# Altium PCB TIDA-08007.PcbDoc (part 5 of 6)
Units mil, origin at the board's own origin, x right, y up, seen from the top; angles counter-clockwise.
Board outline 4212.6 x 2047.24 mil, 10 copper layers (Top Layer, GND 1, Signal Layer 1, GND 2, Split PWR 1, Split PWR 2, GND 3, Signal Layer 2, GND 4, Bottom Layer), stack 66.4 mil thick; 291 components, 178 nets, 1281 pads, 873 vias.
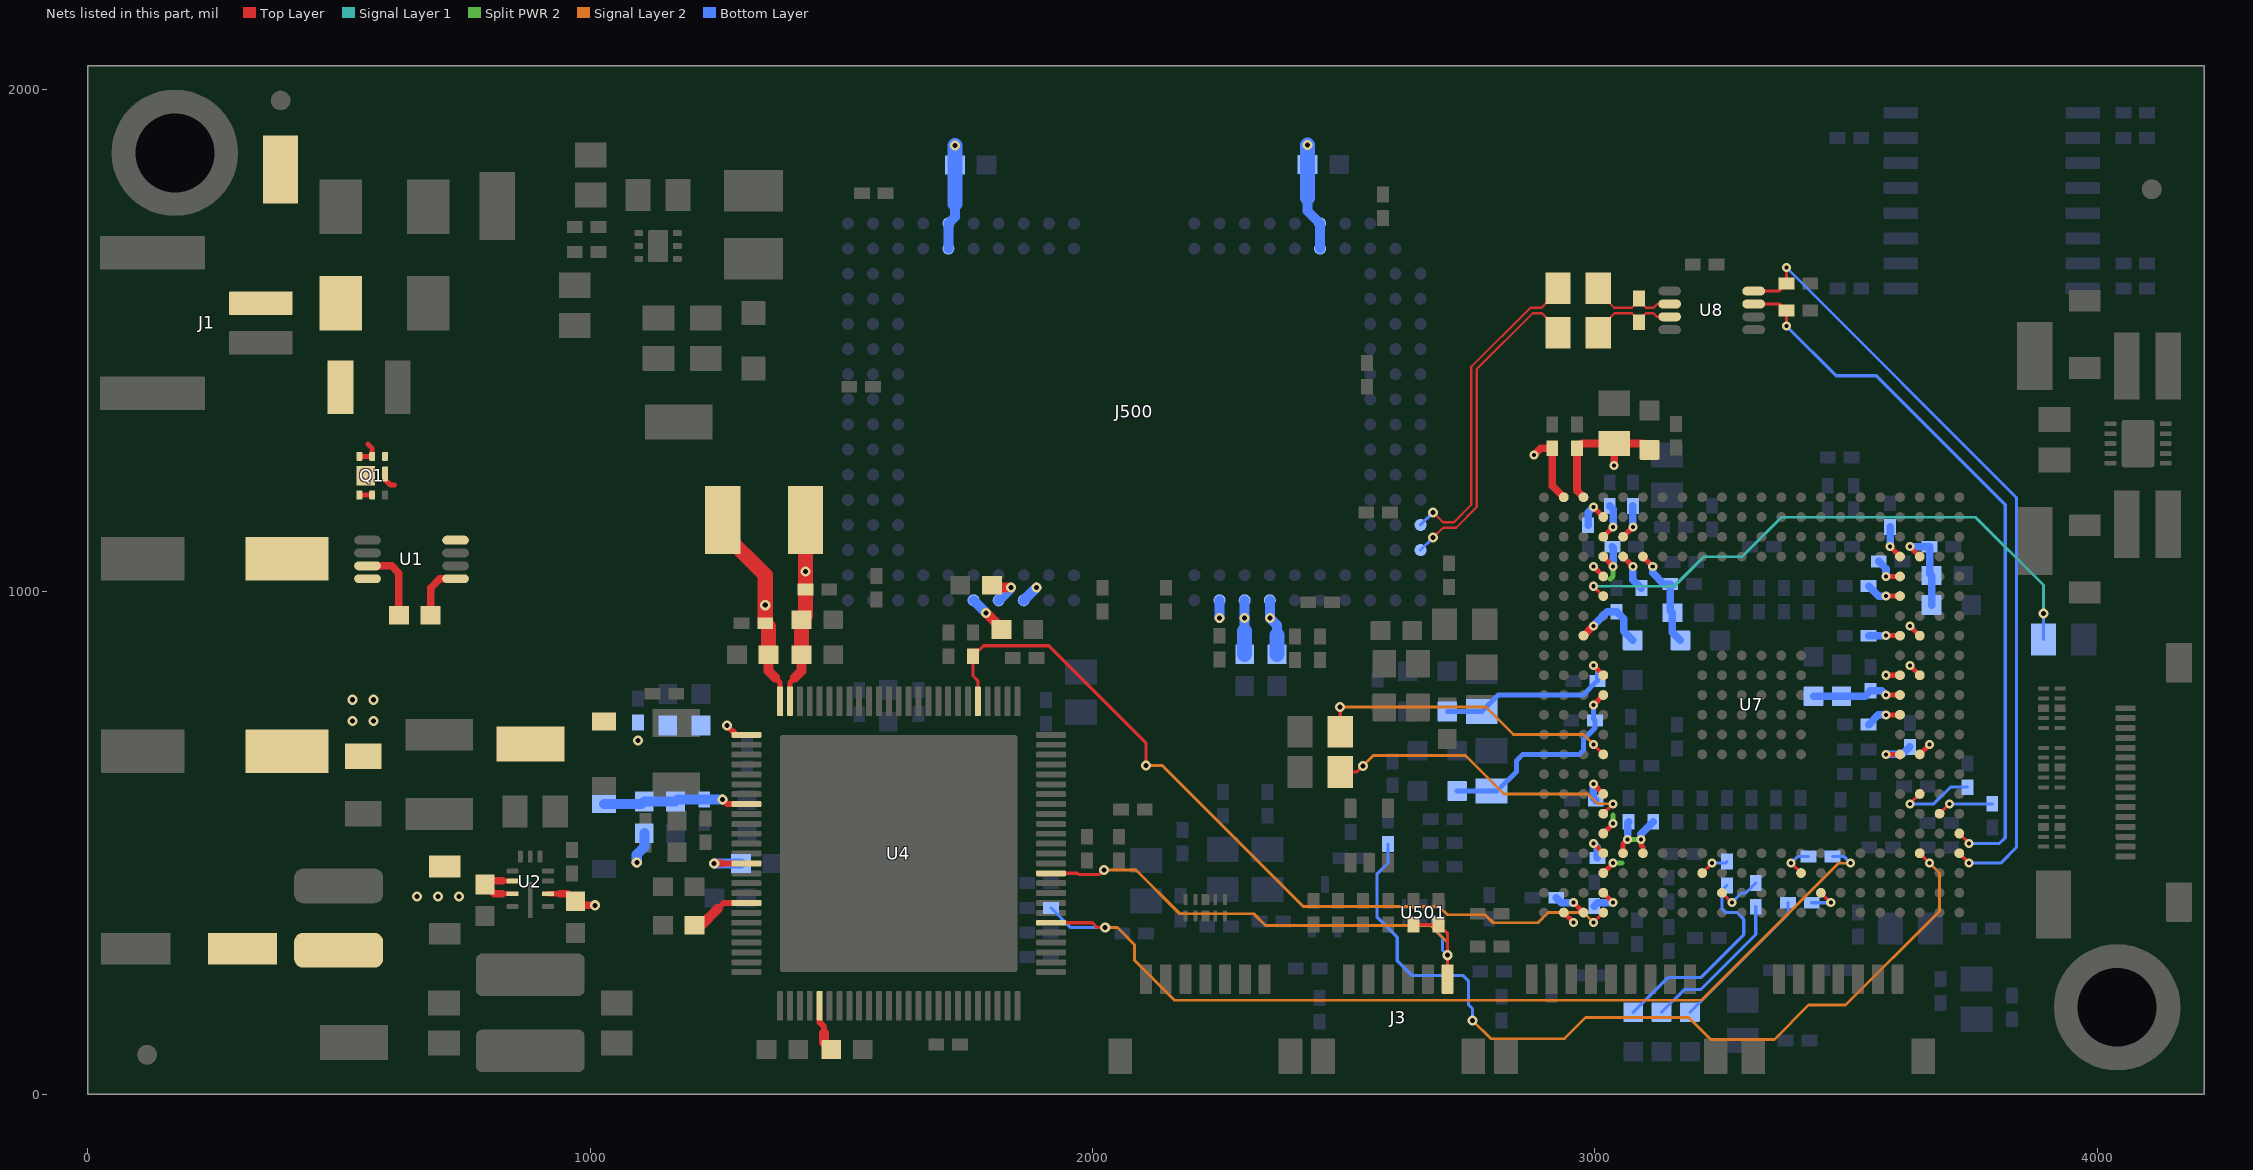
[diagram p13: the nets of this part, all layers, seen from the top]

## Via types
v1: diameter 20, hole 10, Top Layer to Bottom Layer, tented both sides, 439 vias
v2: diameter 18, hole 8, Top Layer to Bottom Layer, tented both sides, 335 vias
v3: diameter 19.68, hole 7.87, Top Layer to Bottom Layer, tented both sides, 72 vias
v4: diameter 19.68, hole 7.87, Top Layer to Bottom Layer, tented bottom, 15 vias
v5: diameter 39.37, hole 19.68, Top Layer to Bottom Layer, 12 vias

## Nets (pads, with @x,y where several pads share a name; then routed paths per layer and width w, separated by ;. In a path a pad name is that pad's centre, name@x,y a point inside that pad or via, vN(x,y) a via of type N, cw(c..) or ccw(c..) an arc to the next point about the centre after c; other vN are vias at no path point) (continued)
PMIC_SPI_MOSI: R7.2 U4.30 U7.D1 | length 1635.8
  Top Layer w6.2: U4.30@1771.65,782.46 1771.65,823.01 1762.08,832.59 R7.2@1762.08,872.03 1782.88,892.83 1912.7,892.83 2106.07,699.46 v1(2106.07,654.79) ; v2(2996.84,342.01) U7.D1@3016.53,361.7
  Signal Layer 2 w5.6: v1(2106.07,654.79) 2138.71,654.79 2419.4,374.1 2689.49,374.1 2706.12,357.47 2781.34,357.47 2797.36,341.46 2886.48,341.46 2906.65,361.63 2977.23,361.63 v2(2996.84,342.01)
PMIC_WD1: R515.2 R543.2 U4.6 | length 1952.1
  Top Layer w6.2: U4.6@1917.32,341.51 1999.75,341.51 2009.47,331.79 v1(2025.16,331.79)
  Signal Layer 2 w5.6: v1(2025.16,331.79) 2049.36,331.79 2083.47,297.68 2083.47,267 2163.16,187.32 3212.34,187.32 3485.15,460.12 v2(3508.65,460.12)
  Bottom Layer w6.2: R543.2@1917.32,371.2 1956.73,331.79 v1(2025.16,331.79) ; R515.2@3472.47,473.68 3495.09,473.68 v2(3508.65,460.12)
PMIC_WD1_S: R515.1 U7.P3 | length 68.1
  Top Layer w6.2: v2(3390.54,460.12) U7.P3@3410.23,440.44
  Bottom Layer w6.2: v2(3390.54,460.12) 3404.1,473.68 R515.1@3425.23,473.68
PROJ_ON: C45.1 J3.6 R17.1 U4.11 U501.2 | length 1125.4
  Top Layer w6.2: U4.11@1917.32,439.94 1969.97,439.94 1972.12,437.78 2014.03,437.78 v1(2022.91,446.65) ; R17.1@2638.48,338.14 C45.1@2688.48,338.14 2706.69,319.93 v1(2706.69,276.86) J3.6@2706.69,229.33
  Signal Layer 2 w5.6: v1(2022.91,446.65) 2086.3,446.65 2173.43,359.52 2320.86,359.52 2344.2,336.18 2672.53,336.18 2706.69,302.01 v1(2706.69,276.86)
  Bottom Layer w6.2: U501.2@2678.64,345.27 2678.64,329.41 2696.53,311.52 2696.53,287.02 v1(2706.69,276.86)
PWM0_OUT: FB504.1 R520.2 | length 417.1
  Bottom Layer w6.2: FB504.1@3075.98,163.29 3145.01,232.32 3210.51,232.32 3295.98,317.79 3295.98,348.34 3282.53,361.79 3260.26,361.79 3252.88,369.17 3252.88,405.93 R520.2@3262.83,415.88
PWM0_OUT_S: R520.1 U7.J3 | length 58.9
  Top Layer w6.2: U7.J3@3213.38,440.44 v2(3233.06,460.12)
  Bottom Layer w6.2: v2(3233.06,460.12) 3259.83,460.12 R520.1@3262.83,463.12
PWM1_OUT: FB503.1 R517.2 | length 307
  Bottom Layer w6.2: FB503.1@3132.48,163.29 3177.55,208.36 3210.14,208.36 3320.02,318.23 R517.2@3320.02,373.51
PWM1_OUT_S: R517.1 U7.K2 | length 91.7
  Top Layer w6.2: U7.K2@3252.75,401.07 v2(3272.43,381.38)
  Bottom Layer w6.2: v2(3272.43,381.38) 3291.74,400.7 3299.96,400.7 R517.1@3320.02,420.75
PWM2_OUT: FB502.1 R514.2 | length 299
  Bottom Layer w6.2: FB502.1@3188.98,163.29 3384.22,358.53 R514.2@3384.22,381.38
PWM2_OUT_S: R514.1 U7.R2 | length 65.7
  Top Layer w6.2: U7.R2@3449.6,401.07 v2(3469.28,381.38)
  Bottom Layer w6.2: R514.1@3431.46,381.38 v2(3469.28,381.38)
RPI_0: R503.2 U7.D17 | length 1145
  Top Layer w6.2: v2(2996.84,1011.31) U7.D17@3016.53,991.62
  Signal Layer 1 w5.6: v2(2996.84,1011.31) 3157.72,1011.31 3216.47,1070.05 3292.74,1070.05 3371.42,1148.73 3757.7,1148.73 3892.95,1013.47 v1(3892.95,956.82)
  Bottom Layer w6.2: R503.2@3892.95,905.32 v1(3892.95,956.82)
RPI_1: R12.2 U7.D6 | length 624.7
  Top Layer w6.2: R12.2@2492.83,641.47 2525.7,641.47 v1(2537.83,653.61) ; U7.D6@3016.53,558.55 v2(3036.21,578.24)
  Signal Layer 2 w5.6: v1(2537.83,653.61) 2558.69,674.47 2742.33,674.47 2818.8,597.99 2985.89,597.99 3005.65,578.24 v2(3036.21,578.24)
RPI_LS: R13.2 U7.D9 | length 612.3
  Top Layer w6.2: R13.2@2492.83,721.47 v1(2492.83,770.97) ; v2(2996.84,696.35) U7.D9@3016.53,676.66
  Signal Layer 2 w5.6: v1(2492.83,770.97) 2782.75,770.97 2837.44,716.28 2976.9,716.28 v2(2996.84,696.35)
TEMP_N: J500.P1 R23.2 | length 650.1
  Top Layer w4.5: v1(2677.76,1108.39) 2697.26,1127.89 2723.72,1127.89 2764.88,1169.04 2764.88,1443.71 2876.05,1554.89 2894.66,1554.89 2926.48,1523.07 R23.2@2926.48,1516.1
  Bottom Layer w6.2: J500.P1@2652.76,1083.39 v1(2677.76,1108.39)
TEMP_P: J500.N1 R22.2 | length 649.3
  Top Layer w4.5: v1(2677.76,1158.39) 2697.26,1138.89 2719.17,1138.89 2753.88,1173.59 2753.88,1448.27 2871.49,1565.89 2893.3,1565.89 2926.48,1599.07 R22.2@2926.48,1604.68
  Bottom Layer w6.2: J500.N1@2652.76,1133.39 v1(2677.76,1158.39)
TMP411_N: C51.2 R23.1 U8.3 | length 180.7
  Top Layer w4.5: R23.1@3006.48,1516.1 3006.48,1522.62 3038.75,1554.89 3073.24,1554.89 C51.2@3087.46,1540.67 ; C51.2@3087.46,1536.77 C51.2@3087.46,1540.67 ; U8.3@3148.57,1547.59 3123.58,1547.59 3116.28,1554.89 3101.68,1554.89 C51.2@3087.46,1540.67
TMP411_P: C51.1 R22.1 U8.2 | length 181
  Top Layer w4.5: R22.1@3006.48,1604.68 3006.48,1597.65 3038.24,1565.89 3073.11,1565.89 C51.1@3087.46,1580.23 ; C51.1@3087.46,1584.01 C51.1@3087.46,1580.23 ; U8.2@3148.57,1573.18 3123.73,1573.18 3116.43,1565.89 3101.81,1565.89 C51.1@3087.46,1580.23
TMP411_SCL: R25.1 U7.AB4 U8.8 | length 1581.3
  Top Layer w6.2: U8.8@3315.89,1598.77 3365.58,1598.77 R25.1@3381.08,1614.28 v2(3381.08,1645.63) ; U7.AB4@3725.19,479.81 v2(3744.87,460.12)
  Bottom Layer w6.2: v2(3381.08,1645.63) 3838.61,1188.1 3838.61,491.32 3807.42,460.12 v2(3744.87,460.12)
TMP411_SDA: R26.1 U7.AB5 U8.7 | length 1451.4
  Top Layer w6.2: U8.7@3315.89,1573.18 3368.29,1573.18 R26.1@3381.08,1560.39 v2(3381.08,1529.04) ; U7.AB5@3725.19,519.18 v2(3744.87,499.49)
  Bottom Layer w6.2: v2(3381.08,1529.04) 3479.86,1430.26 3559.82,1430.26 3816.48,1173.6 3816.48,510.75 3805.23,499.49 v2(3744.87,499.49)
TSTPT_0: R532.1 U7.Y4 | length 1715.1
  Top Layer w6.2: U7.Y4@3646.45,479.81 v2(3666.13,460.12)
  Signal Layer 2 w5.6: v1(2756.17,147.09) 2792.45,110.8 2939.09,110.8 2981.24,152.96 3186.67,152.96 3230.33,109.31 3356.97,109.31 3425.22,177.55 3498.71,177.55 3685.47,364.3 3685.47,440.79 v2(3666.13,460.12)
  Bottom Layer w6.2: R532.1@2587.97,498.01 2587.97,460.59 2566.33,438.95 2566.33,352.54 2606.51,312.36 2606.51,265.87 2635.5,236.88 2736.99,236.88 2748.47,225.4 2748.47,177.92 2756.17,170.22 v1(2756.17,147.09)
TSTPT_5: R506.1 U7.AA6 | length 113.1
  Top Layer w6.2: U7.AA6@3685.82,558.55 v2(3705.5,578.24)
  Bottom Layer w6.2: v2(3705.5,578.24) R506.1@3790.72,578.24
TSTPT_6: R508.1 U7.Y7 | length 156.4
  Top Layer w6.2: v2(3626.76,578.24) U7.Y7@3646.45,597.92
  Bottom Layer w6.2: v2(3626.76,578.24) 3674.57,578.24 3707.7,611.36 R508.1@3741.58,611.36
V_BIAS: C23.1 C33.1 C570.1 J500.T7 J500.T15 R4.2 TP6.1 U4.50 | length 602
  Top Layer w10: 1367.95,829.64 1377.95,819.64 U4.50@1377.95,782.46
  Top Layer w20: C23.1@1354.95,874.85 1354.95,842.86 1367.95,829.86 ; v1(1787.99,958.39) 1818.84,927.54 C33.1@1818.84,925.44
  Top Layer w30: TP6.1@1263.98,1143.15 1263.98,1117.9 1348.43,1033.45 v1(1348.43,973.53) R4.2@1348.43,937.78 1354.95,931.25 C23.1@1354.95,874.92
  Bottom Layer w20: J500.T15@1762.99,983.39 v1(1787.99,958.39) ; J500.T7@2352.76,983.39 v1(2352.76,948.03) 2366.91,933.88 2366.91,914.39
  Bottom Layer w30: C570.1@2366.91,875.98 2366.91,914.39
V_OFFSET: C25.1 C26.1 C567.1 C577.1 J500.A5 J500.A16 J500.B5 J500.B16 J500.T9 J500.T13 R5.2 TP7.1 U4.49 | length 870.7
  Top Layer w10: U4.49@1397.64,782.46 1397.64,819.64 1407.64,829.64
  Top Layer w20: 1407.64,829.86 1420.64,842.86 C26.1@1420.64,874.85
  Top Layer w30: C26.1@1420.64,874.85 C25.1@1420.64,944.48 1428.51,952.36 R5.2@1428.51,1005.07 v1(1428.51,1040.82) TP7.1@1428.51,1143.15
  Bottom Layer w20: J500.B16@1712.99,1683.39 J500.A16@1712.99,1733.39 1725.91,1746.31 1725.91,1772.52 ; J500.T13@1862.99,983.39 v1(1887.99,1008.39) ; v1(2252.76,948.03) J500.T9@2252.76,983.39 ; 2427.76,1784.1 2427.76,1758.39 J500.A5@2452.76,1733.39 J500.B5@2452.76,1683.39
  Bottom Layer w30: 1725.91,1772.52 C577.1@1725.91,1849.63 v1(1725.91,1888.33) ; 2427.76,1784.1 C567.1@2427.76,1850.8 v1(2427.76,1889.51)
V_RESET: C32.1 C571.1 C585.1 C587.1 D3.2 J500.T8 J500.T14 R547.2 TP4.1 U4.51 | length 229.6
  Top Layer w11.81: v1(1272.3,733.98) 1290.75,715.53 U4.51@1311.02,715.53
  Top Layer w20: C32.1@1799.61,1013.39 1804.61,1008.39 v1(1837.99,1008.39)
  Bottom Layer w20: J500.T14@1813.03,983.35 J500.T14@1812.99,983.39 v1(1837.99,1008.39) ; 2302.76,922.23 v1(2302.76,948.03) J500.T8@2302.76,983.39
  Bottom Layer w30: C571.1@2302.76,875.98 2302.76,922.23
  other v1: 1095.5,704.37
VCAPH: C5.1 U1.7 | length 152.4
  Top Layer w15: U1.7@556.78,1051.86 605.1,1051.86 619.35,1037.62 C5.1@619.35,953.65
VCAPL: C5.2 U1.1 | length 111.3
  Top Layer w15: C5.2@682.34,953.65 682.34,1007.8 700.55,1026 U1.1@731.98,1026
VCC3IO_COSC: C549.1 FB506.2 U7.C15 | length 155.9
  Top Layer w15: U7.C15@2977.16,912.88 v2(2996.84,932.57)
  Bottom Layer w15: v2(2996.84,932.57) 3024.77,960.5 C549.1@3043.1,960.5 3056.86,946.74 3056.86,921.52 FB506.2@3074.9,903.48
VCC11A_DDI: C535.1 C538.1 C543.1 C544.1 C548.1 FB505.2 U7.E4 U7.E19 U7.F4 U7.F19 | length 450.8
  Top Layer w10: U7.E4@3055.9,479.81 3055.9,498.52 v2(3065.02,507.65) ; U7.E19@3055.9,1070.36 v2(3075.58,1050.68) ; v2(3091.53,507.65) 3091.53,496.45 3095.27,492.71 U7.F4@3095.27,479.81 ; U7.F19@3095.27,1070.36 v2(3114.95,1050.68)
  Split PWR 2 w10: v2(3065.02,507.65) v2(3091.53,507.65)
  Bottom Layer w15: v2(3065.02,507.65) 3065.02,540.4 C548.1@3067.02,542.4 ; v2(3075.58,1050.68) 3075.58,1024.48 C544.1@3092.31,1007.74 ; v2(3091.53,507.65) 3091.53,518.06 C543.1@3115.88,542.4 ; v2(3114.95,1050.68) 3114.95,1037.95 3137.22,1015.68 C538.1@3149.95,1015.68 3149.95,962.65 C535.1@3154.06,958.54 3154.06,919.43 FB505.2@3169.93,903.55
VCC11A_LVDS: C508.1 C512.1 C515.1 C518.1 C522.1 FB501.2 U7.W11 U7.W12 U7.W17 U7.W18 | length 385.1
  Top Layer w10: v2(3579.24,755.4) U7.W11@3607.08,755.4 ; v2(3579.24,794.77) U7.W12@3607.08,794.77 ; v2(3579.24,991.62) U7.W17@3607.08,991.62 ; v2(3579.24,1030.99) U7.W18@3607.08,1030.99
  Bottom Layer w15: FB501.2@3435.02,792.31 C522.1@3490.92,792.31 3537.4,792.31 C518.1@3548.37,803.27 3570.74,803.27 v2(3579.24,794.77) ; C512.1@3544.49,736.03 3563.86,755.4 v2(3579.24,755.4) ; C515.1@3544.49,1011.62 3564.49,991.62 v2(3579.24,991.62) ; C508.1@3564.77,1060.7 3579.24,1046.23 v2(3579.24,1030.99)
VCC11AD_PLLD: C555.1 C562.1 FB508.2 U7.D12 | length 426.2
  Top Layer w10: v2(2996.84,775.09) U7.D12@3016.53,794.77
  Bottom Layer w10: FB508.2@2725.72,603.98 C562.1@2794.05,603.98 2805.31,603.98 2844.09,642.76 2844.09,664.4 2856.35,676.66 2968.48,676.66 2977.45,685.64 2977.45,706.33 3000.09,728.97 C555.1@3000.09,744.27 2996.84,747.53 v2(2996.84,775.09)
VCC11AD_PLLM: C552.1 C563.1 FB510.2 U7.D13 | length 385.8
  Top Layer w10: v2(2996.84,853.83) U7.D13@3016.53,834.14
  Bottom Layer w10: FB510.2@2706.11,761.98 C563.1@2774.43,761.98 2807.22,794.77 2976.47,794.77 C552.1@3004.71,823.01 3004.71,845.95 v2(2996.84,853.83)
VCC18A_LVDS: C48.1 C49.1 C50.1 C545.1 C546.1 C551.1 C553.1 C554.1 C556.1 C558.1 C559.1 FB1.2 U7.B1 U7.B22 U7.C1 U7.C22 U7.D2 U7.D3 U7.D4 U7.D5 U7.D7 U7.D18 U7.D19 U7.D20 U7.D21 U7.E20 | length 1157.1
  Top Layer w10: U7.B1@2937.79,361.7 v2(2957.47,342.01) ; v2(2957.47,381.38) U7.C1@2977.16,361.7 ; v2(2996.84,499.49) U7.D4@3016.53,479.81 ; v2(2996.84,617.61) U7.D7@3016.53,597.92 ; v2(2996.84,1050.68) U7.D18@3016.53,1030.99 ; v2(2996.84,1168.79) U7.D21@3016.53,1149.1 ; U7.D2@3016.53,401.07 v2(3036.21,381.38) ; U7.D3@3016.53,440.44 v2(3036.21,460.12) ; U7.D5@3016.53,519.18 v2(3036.21,538.86) ; U7.D19@3016.53,1070.36 v2(3036.21,1050.68) ; U7.D20@3016.53,1109.73 v2(3036.21,1129.42) ; U7.E20@3055.9,1109.73 v2(3075.58,1129.42)
  Top Layer w15: v2(2878.73,1272.82) 2891.75,1285.84 C48.1@2914.84,1285.84 2914.84,1211.41 U7.B22@2937.79,1188.47 ; U7.C22@2977.16,1188.47 2964.21,1201.41 C49.1@2964.21,1285.84 2973.84,1295.47 C50.1@3038.27,1295.47 ; v2(3038.27,1251.95) C50.1@3038.27,1295.47 ; FB1.2@3108.54,1282.65 3095.73,1295.47 C50.1@3038.27,1295.47
  Split PWR 2 w10: 3030.19,1025.33 3036.21,1031.35 v2(3036.21,1050.68) ; v2(3036.21,460.12) 3053.48,460.12 ; v2(3036.21,538.86) 3036.21,556.14
  Bottom Layer w15: C559.1@2922.72,391.38 2932.72,381.38 v2(2957.47,381.38) ; C558.1@2986.84,1132.72 2986.84,1158.79 v2(2996.84,1168.79) ; v2(2996.84,499.49) 3004.71,491.62 C553.1@3004.71,470.68 ; v2(2996.84,617.61) 2996.84,589.52 C554.1@3001.5,584.86 ; C556.1@2998.59,374.76 3005.21,381.38 v2(3036.21,381.38) ; C551.1@3029.29,1171.02 3036.21,1164.09 v2(3036.21,1129.42) ; C545.1@3034.53,1090.05 3036.21,1088.36 v2(3036.21,1050.68) ; v2(3075.58,1129.42) C546.1@3075.58,1171.02
VCC33A_LVDS: C501.1 C502.1 C507.1 C510.1 C517.1 FB500.2 U7.W9 U7.W13 U7.W15 U7.W19 U7.Y9 U7.Y13 U7.Y15 U7.Y19 | length 507.7
  Top Layer w10: v2(3579.24,676.66) U7.W9@3607.08,676.66 ; v2(3579.24,834.14) U7.W13@3607.08,834.14 ; v2(3579.24,912.88) U7.W15@3607.08,912.88 ; v2(3587.39,1090.05) U7.W19@3607.08,1070.36 ; v2(3626.76,853.83) U7.Y13@3646.45,834.14 ; v2(3626.76,932.57) U7.Y15@3646.45,912.88 ; v2(3626.76,1090.05) U7.Y19@3646.45,1070.36 ; U7.Y9@3646.45,676.66 v2(3666.13,696.35)
  Bottom Layer w15: C517.1@3544.49,912.88 v2(3579.24,912.88) ; v2(3579.24,676.66) 3611.76,676.66 C507.1@3626.76,691.66 ; v2(3587.39,1090.05) C510.1@3587.39,1129.42 ; v2(3626.76,1090.05) C502.1@3666.13,1090.05 3666.13,1036.43 C501.1@3670.07,1032.5 FB500.2@3670.07,973.94
VIN: C4.1 D2.2 J1.1 Q1.4 Q1.7 TP1.1 U1.4 | length 34.4
  Top Layer w10: Q1.7@591.7,1235.06 591.7,1223.45 601.36,1213.79 601.43,1213.79 602.62,1212.6 609.97,1212.6
VIN_FILT: C3.1 C8.2 C9.1 C13.1 L1.2 U2.2 U2.9 U2.10 | length 222.4
  Top Layer w9.84: 824.61,399.23 U2.10@845.26,399.23 ; 825.45,424.82 U2.9@845.26,424.82
  Top Layer w10: U2.2@916.13,399.23 939.21,399.23
  Top Layer w15: 824.61,399.23 809.4,399.23 C9.1@790.7,417.93 797.59,424.82 825.45,424.82 ; 939.21,399.23 955.73,399.23 C13.1@970.7,384.27 978.65,376.31 v1(1009.3,376.31)
  other v1: 654.92,393.59 696.98,393.59 739.04,393.59
VIN_PROT: C1.1 C2.1 L2.1 Q1.1 Q1.2 Q1.5 Q1.6 Q1.8 R546.2 U1.8 | length 144.1
  Top Layer w10: Q1.1@540.51,1192.94 Q1.2@566.11,1192.94 ; Q1.6@540.51,1269.71 Q1.5@566.11,1269.71 566.11,1285.87 557.34,1294.64
  Bottom Layer w20: v1(1092.69,461.67) 1092.69,477.18 1107.69,492.18 R546.2@1107.69,519.86
  other v1: 526.83,743.27 568.94,743.27 526.83,785.38 568.94,785.38
VLDOA_3P3: C27.1 U4.80 | length 96.5
  Top Layer w11.81: U4.80@1456.69,176.16 1456.69,143.3 1465.75,134.24 1465.75,122.04
  Top Layer w20: 1465.75,122.04 1465.75,103.1 C27.1@1479.69,89.16
VLDOT_3P3V: C18.1 U4.68 | length 121.5
  Top Layer w11.81: 1253.39,368.95 1265.33,380.88 U4.68@1311.02,380.88
  Top Layer w20: C18.1@1207.85,336.63 1221.07,336.63 1253.39,368.95
VLDOT_5V: C581.1 U4.64 | length 117.3
  Top Layer w11.81: 1262.07,459.62 U4.64@1311.02,459.62
  Top Layer w15: v1(1246.9,459.62) 1262.07,459.62
  Bottom Layer w20: v1(1246.9,459.62) C581.1@1300.02,459.62
VMAIN_DIV: C586.1 D500.1 R545.2 R546.1 U4.58 | length 290.9
  Top Layer w11.81: v1(1263.3,586.96) 1272.52,577.74 U4.58@1311.02,577.74
  Bottom Layer w20: D500.1@1027.75,577.69 1102.54,577.69 R546.1@1107.69,582.85 R545.2@1170.02,582.85 1174.13,586.96 C586.1@1227.06,586.96 v1(1263.3,586.96)
pads on no net: FID1.1 FID2.1 FID3.1 FID500.1 FID501.1 FID502.1 J500.A14 J500.B6 J500.B7 J500.B14 J500.M18 J500.M19 J500.N3 J500.N18 J500.P18 J500.P19 J500.R12 J500.R16 J500.R17 J500.R18 J500.R19 J500.T11 J500.T12 J500.T17 J500.T18 Q1.0 U1.3 U1.5 U2.8 U3.7@1135,1670.79 U3.7@1135,1706.22 U4.12 U4.15 U4.38 U4.39 U4.40 U4.41 U4.43 U4.44 U4.45 U4.46 U4.47 U4.57 U4.61 U4.62 U4.63 U4.69 U4.70 U4.73 U4.74 U4.85 U4.86 U4.88 U4.90 U4.92 U4.93 U4.94 U5.3@2224.41,355.21 U5.6 U5.7 U5.8@2224.41,388.09 U5.9 U5.10 U7.AA3 U7.AA4 U7.AA5 U7.AA7 U7.AA15 U7.AA16 U7.AA17 U7.AA18 U7.AA19 U7.AB3 U7.AB6 U7.AB7 U7.AB15 U7.AB16 U7.AB17 U7.AB18 U7.AB19 U7.C10 U7.C11 U7.D22 U7.E21 U7.E22 U7.F20 U7.F21 U7.F22 U7.G20 U7.G21 U7.G22 U7.H3 U7.H20 U7.J20 U7.K3 U7.K20 U7.L1 U7.L2 U7.L3 U7.M1 U7.M2 U7.M3 U7.M20 U7.N1 U7.N2 U7.N3 U7.N20 U7.P1 U7.P2 U7.R1 U7.R3 U7.T1 U7.T2 U7.T3 U7.U1 U7.U2 U7.U3 U7.V1 U7.V3 U7.Y5 U7.Y6 U8.4 U8.6 U9.3@3925.83,768.49 U9.4 U9.5 U9.6 U9.7 U9.8@3892.95,768.49 U9.9 U9.10 U10.3@3925.83,650.38 U10.6 U10.7 U10.8@3892.95,650.38 U10.9 U10.10 U11.3@3925.83,532.27 U11.6 U11.7 U11.8@3892.95,532.27 U11.9 U11.10 U500.4 U500.5 U500.6 U500.11 U500.12 U500.13 U500.14 U501.3@2658.95,345.27 U501.5 U501.6 U501.7 U501.8@2658.95,378.14 U501.9 U501.10
copper on no net: | length 4957.4
  Top Layer w10: 264.79,32.32 398.33,32.32 398.33,146.65 264.79,146.65 264.79,32.32
  Split PWR 1 w10: 264.79,32.32 264.79,146.65 398.33,146.65 398.33,32.32 264.79,32.32
  Split PWR 2 w10: 264.79,32.32 264.79,146.65 398.33,146.65 398.33,32.32 264.79,32.32
  Signal Layer 2 w10: 264.79,32.32 264.79,146.65 398.33,146.65 398.33,32.32 264.79,32.32
  GND 4 w10: 264.79,32.32 264.79,146.65 398.33,146.65 398.33,32.32 264.79,32.32
  GND 1 w10: 264.79,32.32 264.79,146.65 398.33,146.65 398.33,32.32 264.79,32.32
  Signal Layer 1 w10: 264.79,32.32 398.33,32.32 398.33,146.65 264.79,146.65 264.79,32.32
  GND 2 w10: 264.79,32.32 264.79,146.65 398.33,146.65 398.33,32.32 264.79,32.32
  GND 3 w10: 264.79,32.32 264.79,146.65 398.33,146.65 398.33,32.32 264.79,32.32
  Bottom Layer w10: 264.79,32.32 264.79,146.65 398.33,146.65 398.33,32.32 264.79,32.32

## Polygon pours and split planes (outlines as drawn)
1.1V on Top Layer "TOP_LAYER_1.1V_P2583" (solid, remove dead copper, pour order 2583): 3954.05,1229.51 3954.05,1274.07 3965.83,1285.85 4052.54,1285.85 4060.02,1278.37 4060.02,1236.23 4066.12,1230.14 4082.5,1230.14 4082.5,1038.57 3944.16,1038.57 3911.47,1005.88 3823.08,1005.88 3798.79,1030.18 3798.78,1206.28 3814.21,1221.71 3946.25,1221.71
1.8V on Top Layer "TOP_LAYER_1.8V_P2581" (solid, remove dead copper, pour order 2581): 3800.5,1566.03 3800.5,1398.97 3820.13,1379.34 3950.62,1379.33 3954.06,1375.9 3954.05,1337.26 3962.54,1328.77 4055.56,1328.77 4087.99,1328.77 4087.99,1543.51 3936.02,1543.51 3900.6,1578.92 3813.4,1578.92
GND on Top Layer "TOP_LAYER_GND_P2582" (solid, remove dead copper, pour order 2582): 2741.2,734.75 2753.23,722.72 2753.23,686.33 2737.12,669.65 2559.98,669.65 2488.9,740.73 2488.9,942.93 2520.93,974.96 2678.65,974.96 2703.76,949.86 2703.76,817.53 2694.09,807.86 2617.2,807.86 2613.1,803.76 2613.1,742.63 2620.98,734.75
VIN_PROT on Top Layer "TOP_LAYER_VIN_PROT_P2590" (solid, remove dead copper, pour order 2590): 280.52,1287.76 280.52,639.68 297.81,622.39 592.9,622.39 601.9,631.39 601.9,820.12 572.29,849.73 572.29,973.48 600.6,1001.79 600.6,1067.59 580.22,1087.97 580.22,1161.15 580.22,1279.3 545.47,1314.05 306.81,1314.05
GND on Top Layer "TOP_LAYER_GND_P2591" (solid, remove dead copper, pour order 2591): 217.05,359 252.82,359 265.38,371.56 265.38,1293.97 300.53,1329.13 415.49,1329.13 433.46,1347.1 433.46,1497.72 428.89,1502.29 274.56,1502.29 243.79,1533.05 243.79,1618.35 305.21,1679.77 305.21,2047.25 0,2047.25 0,0 191.44,0 191.44,333.39
11SW1 on Top Layer "TOP_LAYER_11SW1_P2575" (solid, remove dead copper, pour order 2575): 4120.79,1266.84 4097.12,1243.17 4097.12,1045.97 4104.52,1038.57 4176.1,1038.57 4186.39,1048.86 4186.39,1246.93 4166.49,1266.84
18SW2 on Top Layer "TOP_LAYER_18SW2_P2576" (solid, remove dead copper, pour order 2576): 4095.61,1541.66 4095.61,1339.12 4109.31,1325.42 4166.36,1325.42 4171.54,1330.6 4171.54,1345.17 4186.6,1360.23 4186.6,1537.51 4173.47,1550.64 4104.59,1550.64
NetC6_1 on Top Layer "TOP_LAYER_NETC6_1_P2587" (solid, remove dead copper, pour order 2587): 280.52,589.74 280.52,372.07 293.49,359.1 592.98,359.1 609.32,375.43 609.32,472.93 640.33,503.94 794.75,503.94 804.32,513.51 804.32,596.94 794.07,607.2 297.97,607.2
VIN on Top Layer "TOP_LAYER_VIN_P2589" (solid, remove dead copper, pour order 2589): 258.98,1611.91 258.98,1540.05 268.87,1530.15 443.11,1530.15 443.11,1351.59 463.35,1331.35 549.55,1331.35 581.3,1299.6 581.3,1214.9 590.29,1205.91 605.46,1205.91 655.2,1156.17 655.2,1099.3 665.58,1088.92 787.48,1088.92 799.89,1101.33 799.89,1206.93 670.16,1336.66 590.86,1336.66 573.17,1354.35 573.17,1666.44 559.42,1680.19 463.51,1680.19 452.46,1691.25 452.46,1913.32 440.87,1924.91 327.81,1924.91 320.86,1917.95 320.86,1673.79
6.5V on Top Layer "TOP_LAYER_6.5V_P2584" (solid, remove dead copper, pour order 2584): 1068.9,1505.52 1272.81,1505.52 1287.85,1490.48 1367.35,1490.48 1373.96,1483.87 1373.96,1296.88 1357.84,1280.76 1079.11,1280.76 1056.49,1303.38 1056.49,1493.1
65SW on Top Layer "TOP_LAYER_65SW_P2579" (solid, remove dead copper, pour order 2579): 1161.33,1663.29 1161.33,1621.66 1173.28,1609.71 1241.84,1609.71 1280.94,1570.61 1280.94,1519.66 1294.98,1505.62 1429.93,1505.62 1469.54,1545.23 1469.54,1687.29 1438.52,1718.31 1242.59,1718.31 1192.2,1667.92 1165.96,1667.92
3.3V on Top Layer "TOP_LAYER_3.3V_P2588" (solid, remove dead copper, pour order 2588): 429.83,170.85 438.91,179.92 597.76,179.92 630.75,146.93 1144.76,146.93 1158.55,133.14 1158.55,0 429.83,0
GND on Top Layer "TOP_LAYER_GND_P2578" (solid, remove dead copper, pour order 2578): 740.87,1862.18 740.87,1695.39 764.58,1671.68 893.53,1671.68 914.09,1692.25 914.09,1856.34 889.02,1881.42 760.11,1881.42
GND on Top Layer "TOP_LAYER_GND_P2577" (solid, remove dead copper, pour order 2577): 627.57,659.59 777.52,659.59 782.8,664.87 782.8,807.38 775.56,814.62 633,814.62 617.13,798.76 617.13,670.03
VIN_FILT on Top Layer "TOP_LAYER_VIN_FILT_P2586" (solid, remove dead copper, pour order 2586): 209.6,330.17 209.6,208.58 223.03,195.14 651.03,195.14 665.12,209.23 665.12,346.33 680.76,361.97 835.52,361.97 868.21,394.66 868.21,445.33 856.42,457.11 818.68,494.85 652.56,494.85 624.59,466.88 624.59,369.12 599.3,343.84 223.26,343.84
GND on Top Layer "TOP_LAYER_GND_P2573" (solid, remove dead copper, pour order 2573): 4069.81,802.96 4080.06,792.71 4193.54,792.71 4199.69,798.87 4199.69,911.72 4187.23,924.19 4080.3,924.19 4069.81,913.7
GND on Top Layer "TOP_LAYER_GND_P2574" (solid, remove dead copper, pour order 2574): 4069.81,326.58 4080.06,316.33 4193.54,316.33 4199.69,322.49 4199.69,435.35 4187.23,447.81 4080.3,447.81 4069.81,437.32
3.3V on Top Layer "TOP_LAYER_3.3V_P2585" (solid, remove dead copper, pour order 2585): 1168.38,1730.06 1134.62,1730.06 1130.74,1733.93 1130.74,1939.33 1143.47,1952.05 1435.13,1952.06 1452.03,1935.15 1452.03,1754.81 1438.88,1741.67 1215.35,1741.67 1197.81,1724.13 1197.81,1684.64 1188.65,1675.47 1173.94,1675.47 1168.38,1681.02
V_RESET on Top Layer "TOP_LAYER_V_RESET_P2580" (solid, remove dead copper, pour order 2580): 797.93,804.45 797.93,649.78 803.37,644.34 983.3,644.34 1009.46,670.51 1103.34,670.51 1117.88,685.05 1117.88,782.83 1082.74,817.97 811.45,817.97
VIN_PROT on Signal Layer 1 "SIGNAL_LAYER_1_VIN_PROT_P2607" (solid, remove dead copper, pour order 2607): 479.22,815.07 479.22,603.49 560,522.71 938.19,522.71 1029.21,431.69 1147.27,431.69 1160.38,444.8 1160.38,569.99 883.41,846.97 511.11,846.97
VIN_FILT on Signal Layer 1 "SIGNAL_LAYER_1_VIN_FILT_P2606" (solid, remove dead copper, pour order 2606): 623.19,424.06 623.19,276.04 647.73,251.51 1019.78,251.51 1046.22,277.95 1046.22,373.02 975.21,444.03 643.16,444.03
VCC11A_DDI on Split PWR 2 "SPLIT_PWR_2_VCC11A_DDI_P2598" (solid, remove dead copper, pour order 2598): 3041.04,517.26 3041.04,491.39 3052.3,480.12 3135.95,480.12 3139.77,483.94 3149.9,494.07 3149.9,566.82 3115.14,601.58 3115.14,705.88 3044.03,776.99 3044.03,827.66 3060.98,844.61 3130.94,844.61 3145.39,859.06 3145.39,1054.03 3126.01,1073.41 3065,1073.41 3053.52,1061.93 3053.52,1016.27 3042.06,1004.81 2940.43,1004.81 2927.39,991.76 2927.39,669.05 2935.06,661.37 3020.82,661.37 3056.31,625.88 3056.31,532.54 3048.13,524.36
V_BIAS on Split PWR 2 "SPLIT_PWR_2_V_BIAS_P2599" (solid, remove dead copper, pour order 2599): 2327.3,967.43 2335.05,975.17 2482.24,975.17 2490.31,967.1 2490.31,801.26 2464.72,775.68 1818.89,775.68 1708.98,885.59 1591.64,885.59 1570.03,863.99 1570.03,813.82 1554.48,798.27 1395.63,798.27 1310.85,883.05 1310.85,1000.66 1327.28,1017.09 1367.53,1017.09 1401.24,983.39 1801.45,983.39 1887.62,897.21 2307.64,897.21 2327.3,916.87
VCC33A_LVDS on Split PWR 2 "SPLIT_PWR_2_VCC33A_LVDS_P2597" (solid, remove dead copper, pour order 2597): 3538.11,1114.69 3538.11,629.76 3556.25,611.61 3677.52,611.61 3688.4,622.49 3688.4,1120.54 3679.53,1129.42 3552.84,1129.42
V_OFFSET on Split PWR 2 "SPLIT_PWR_2_V_OFFSET_P2601" (solid, remove dead copper, pour order 2601): 2311.88,924.51 2311.88,974.13 2324.87,987.12 2691.71,987.11 2712.32,1007.73 2712.32,1886.83 2673,1926.15 2432.13,1926.16 2431.6,1926.68 1422.01,1926.68 1383.66,1888.33 1383.29,1136.62 1383.29,1022.9 1407.56,998.63 1807.42,998.63 1893.69,912.36 2299.73,912.36
VCC18A_LVDS on Split PWR 2 "SPLIT_PWR_2_VCC18A_LVDS_P2600" (solid, remove dead copper, pour order 2600): 3058.45,606.7 3010.89,654.25 2930.24,654.25 2917.96,666.53 2917.96,998.36 2934.97,1015.37 3034.22,1015.37 3047.66,1028.81 3047.66,1078.08 3058.17,1088.59 3079.13,1088.59 3113.99,1123.44 3113.99,1289.2 3090.18,1313.01 2754.29,1313.01 2727.39,1286.11 2727.39,367.41 2782.43,312.37 3047.66,312.37 3077.71,342.42 3077.71,469.8 3032.48,469.8 3032.48,529.78 3058.45,529.78
3.3V on Split PWR 2 "SPLIT_PWR_2_3.3V_P2602" (solid, remove dead copper, pour order 2602): 4212.6,2044.53 4212.6,0 0,0 0,2047.24
VCC11A_LVDS on Split PWR 1 "SPLIT_PWR_1_VCC11A_LVDS_P2592" (solid, remove dead copper, pour order 2592): 3534.31,982.13 3543.74,972.7 3605.56,972.7 3621.13,957.13 3621.13,889.29 3603,871.15 3542.49,871.15 3534.31,862.97 3534.31,751.17 3544.15,741.32 3795.44,741.32 3809.37,755.25 3809.37,1040.54 3796.84,1053.07 3543.44,1053.07 3534.31,1043.95
V_RESET on Split PWR 1 "SPLIT_PWR_1_V_RESET_P2593" (solid, remove dead copper, pour order 2593): 1919.21,1072.11 1919.21,991.9 1940.02,971.09 2387.19,971.09 2408.06,950.22 2408.06,773.54 2289.37,654.85 1091.21,654.85 1071.23,674.83 1071.23,883.84 1094.68,907.28 1535.07,907.28 1699.9,1072.11
GND on Split PWR 1 "SPLIT_PWR_1_GND_P2594" (solid, remove dead copper, pour order 2594): 900.13,1052.99 1034.57,1187.42 1034.57,2046.72 900.13,2046.72 0,2046.72 0,0 900.13,0
1.8V on Split PWR 1 "SPLIT_PWR_1_1.8V_P2596" (solid, remove dead copper, pour order 2596): 1050.65,2047.24 1050.65,1180.06 914.93,1044.35 914.93,0 1961.65,0 1733.49,228.16 1733.49,618.19 1715.97,635.71 1088.5,635.71 1056,668.21 1056,890.99 1087.29,922.28 1530.44,922.28 1683.87,1075.72 1934.39,1075.72 1934.38,998.37 1946.57,986.18 2395.81,986.18 2423.29,958.7 2423.29,876.39 2438.39,861.29 2613.17,861.29 2815.99,658.48 3070.93,658.48 3148.94,736.49 3148.94,1122.96 3148.94,1302.86 3192.95,1346.87 4212.6,1346.87 4212.6,2047.24
1.1V on Split PWR 1 "SPLIT_PWR_1_1.1V_P2595" (solid, remove dead copper, pour order 2595): 2809.6,643.35 3077.57,643.35 3163.81,729.6 3163.81,1294.41 3201.17,1331.76 4212.6,1331.76 4212.6,0 1983.97,0 1748.42,235.56 1748.42,618.18 1769.56,639.33 2291.93,639.33 2422.14,769.53 2422.14,826.67 2441.44,845.97 2606.98,845.97 2732.13,720.82
6.5V on Signal Layer 2 "SIGNAL_LAYER_2_6.5V_P2603" (solid, remove dead copper, pour order 2603): 973.87,0 1589.49,0 1589.49,842.71 1351.08,1081.12 1351.11,1746.95 1326.2,1771.85 927.43,1771.85 906.33,1750.76 906.33,1493.36 973.87,1425.82
GND on GND 4 "GND_4_GND_P2604" (solid, remove dead copper, pour order 2604): 0,0 0,2047.24 4212.6,2047.24 4212.6,0
GND on GND 1 "GND_1_GND_P2605" (solid, remove dead copper, pour order 2605): 0,0 0,2047.24 4212.6,2047.24 4212.6,0
GND on GND 2 "GND_2_GND_P2608" (solid, remove dead copper, pour order 2608): 0,0 0,2047.24 4212.6,2047.24 4212.6,0
GND on GND 3 "GND_3_GND_P2609" (solid, remove dead copper, pour order 2609): 0,0 0,2047.24 4212.6,2047.24 4212.6,0
V_RESET on Bottom Layer "BOTTOM_LAYER_V_RESET_P2610" (solid, remove dead copper, pour order 2610): 1071.22,769.16 1284.14,769.16 1296.92,756.38 1296.92,684.61 1284.04,671.73 1074.14,671.73 1062.23,683.65 1062.23,760.16

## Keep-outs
Keep-Out Layer:
  circle w20: c3322.44,1358.27 r108.27
  circle w20: c3067.72,1780.71 r98.43
  circle w20: c842.13,1358.27 r108.27
  circle w20: c826.77,1358.27 r108.27
  circle w20: c3307.09,1358.27 r108.27
  lines w10: 1700.58,1077.68 cw(c1699.43,1107.18) 1670.2,1102.99 1670.2,1613.54 cw(c1699.43,1609.35) 1700.58,1638.86 2464.77,1638.86 cw(c2465.93,1609.35) 2495.16,1613.54 2495.16,1102.99 cw(c2465.93,1107.18) 2464.77,1077.68 1700.66,1077.68
  lines w50: 0,0 4212.6,0 4212.6,2047.24 0,2047.24 0,0
  text ".Layer_Name" at 577,-858.49 h60

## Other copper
Top Layer:
  pour cut-out: 597.95,304.01 597.95,324.02 590.64,331.32 570.64,331.32 575.03,326.93 586.34,326.93 589.95,323.32 589.95,312.01
  pour cut-out: 400.62,304.01 400.62,324.02 407.92,331.32 427.93,331.32 423.54,326.93 412.22,326.93 408.62,323.32 408.62,312.01
  pour cut-out: 597.95,397.52 597.95,377.83 590.33,370.21 570.64,370.21
  pour cut-out: 400.62,397.52 400.62,375.58 405.99,370.21 427.93,370.21
  text "1" at 320.21,59.63 h60
  text ".Layer_Name" at 577,-858.49 h60
Split PWR 1:
  text "5" at 310.21,59.63 h60
  text ".Layer_Name" at 577,-858.49 h60
Split PWR 2:
  pour cut-out: 2407.76,846.67 2447.76,846.67 2447.76,810.49 2407.76,810.49
  text "6" at 310.21,59.63 h60
  text ".Layer_Name" at 577,-858.49 h60
Signal Layer 2:
  text "8" at 310.21,59.63 h60
  text ".Layer_Name" at 577,-858.49 h60
GND 4:
  text "9" at 310.21,59.63 h60
  text ".Layer_Name" at 577,-858.49 h60
GND 1:
  text "2" at 310.21,59.63 h60
  text ".Layer_Name" at 577,-858.49 h60
Signal Layer 1:
  text "3" at 310.21,59.63 h60
  text ".Layer_Name" at 577,-858.49 h60
GND 2:
  text "4" at 310.21,59.63 h60
  text ".Layer_Name" at 577,-858.49 h60
GND 3:
  text "7" at 310.21,59.63 h60
  text ".Layer_Name" at 577,-858.49 h60
Bottom Layer:
  text "10" at 375.21,59.63 h60
  text ".Layer_Name" at 577,-858.49 h60

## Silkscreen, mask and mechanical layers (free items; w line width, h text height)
Top Overlay:
  circle w6: c2058.34,244.6 r8.31
  circle w6: c2461.89,244.6 r8.31
  circle w6: c2826.06,244.6 r8.31
  circle w6: c3318.19,244.6 r8.31
  circle w6: c2655.4,720.58 r8.31
  circle w6: c4045.11,442.78 r8.31
  circle w6: c3956.3,487.75 r8.31
  circle w6: c3956.3,605.86 r8.31
  circle w6: c3956.3,723.97 r8.31
  circle w6: c1964.66,226.08 r8.31
  circle w6: c3999.95,1350.69 r8.31
  circle w6: c924.1,338.43 r8.31
  lines w6.1: 785.98,756.64 785.98,631.45 806.93,610.5 ; 999.75,251.55 1018.74,251.55 ; 1039.97,1427.54 1056.69,1444.25 1083,1444.25 ; 1101.11,445.2 1112.79,456.88 1133.86,456.88 ; 1227.57,238.27 1237.83,248.52 1237.83,292.49 ; 1240.33,775.57 1240.33,786.55 ; 1255.97,467.19 1262.62,460.55 1262.62,205.3 ; 1628.52,947.73 1636.56,939.69 1680.69,939.69 ; 2336.63,420.23 2352.9,403.96 2406.99,403.96 ; 2608.21,422.56 2636.16,450.51 2636.16,468.55 ; 2726.17,380.92 2726.17,316.06 2730.9,311.33 ; 2898.63,317.99 2898.63,303.54 2906.71,295.46 2916.74,295.46 ; 3771.16,1188 3776.88,1188
  text "GND" at 772.69,1913.99 h30
  text "'.PRJ_Number'.PCB_Rev" at 1731.34,1818.61 h108.27
  text "VIN" at 346.05,1669.21 h30
  text "1.8V" at 3805.87,1615.75 h30
  text "6.5V" at 1274.38,1299.05 h30
  text "A22" at 2766.53,1181.59 h30
  text "AB22" at 3816.42,1132.21 h30 r90
  text "V_BIAS" at 1197.44,1065.62 h30 r90
  text "V_OFFSET" at 1365,1037.84 h30 r90
  text "+" at 438.62,956.47 h60
  text "1.1V" at 3811.67,929.66 h30
  text "V_RESET" at 923.2,762.61 h30 r90
  text "+" at 437.71,568.33 h60
  text "AB1" at 3806.09,314.87 h30 r90
  text "A1" at 2929.54,282.61 h30
  text "3.3 V" at 451.7,207.11 h30
  text "+" at 352.77,177.46 h60
  text "HOST_IF_SEL" at 3849.79,142.95 h30 r90
  text ".Layer_Name" at 577,-858.49 h60
Bottom Overlay:
  rectangle: 3895.81,1985.51 3939.59,2000.3
  lines w6.1: 1222.09,622.36 1222.09,636.79 ; 2226.37,530.45 2226.37,630.81 ; 2312.62,531.89 2312.62,628.8 ; 2445.34,479.88 2458.18,479.88 ; 2551.87,517.27 2551.87,628.18 2508.26,671.78 2508.26,867.44 2544.4,903.58 2835.39,903.58 2849.01,889.96 2849.01,563.32 2839.68,553.99 2832.14,553.99 2767.17,553.99 2758.55,545.38 2758.55,437.69 ; 2832.11,1290.49 2832.11,1165.18 2976.55,1020.74 3012.22,1020.74 ; 2871.62,155.91 2871.62,174.25 2879.24,181.87 ; 2905.11,591.16 2918.72,591.16 ; 2955.62,354.5 2966.95,354.5 ; 3048.72,31.45 3162.09,31.45 3184.2,53.56 ; 3050.76,276.5 3050.76,267.86 3076.91,241.71 3245.27,241.71 3322.16,318.6 3438.79,318.6 3484.35,364.16 3484.35,439.67 ; 3082.02,787.36 3089.73,795.07 3103.58,795.07 ; 3373.61,196.98 3373.61,219.52 ; 3393.77,878.3 3406.78,891.31 3406.78,924.07 ; 3401.34,1174.59 3409.83,1166.1 3409.83,1134.79 3426.45,1118.17 ; 3542.8,278.26 3542.8,257.74 3549.09,251.45 ; 3547.99,1214.28 3561.19,1227.47 3561.19,1359.06 ; 3581.57,1007.02 3607.65,980.95 3607.65,953.7 ; 3583.65,782.15 3790.87,782.15 3806.04,797.32 ; 3588.17,521.96 3594.13,527.92 3594.13,581.33 ; 3624.07,1094.34 3624.07,1122.41 ; 3681.91,687.15 3681.94,644.91 ; 3744.96,522.13 3757.04,510.06 3757.04,465.27 ; 4134.35,1918.09 4146.16,1918.09 ; 310.74,723.43 332.52,701.65 877.05,701.65 898.3,722.9 898.3,1027.33 872.84,1052.79 334.94,1052.79 310.74,1028.58 310.74,723.43 ; 339.99,439.89 359.27,420.61 849.96,420.61 874.29,444.94 874.29,581.7 853.86,602.14 361.06,602.14 339.99,581.07 339.99,439.89 ; 1026.62,1071.34 1049.58,1048.38 1359.41,1048.38 1388.39,1077.36 1388.39,1514.55 1359.17,1543.78 1048.96,1543.78 1026.62,1521.43 1026.62,1071.34
  text "A20" at 1434.39,1723.15 h30
  text "C1" at 2769.6,1621.65 h30
  text "C" at 1408.73,1531.49 h30
  text "T1" at 2771.02,971.41 h30
  text "T20" at 1437.45,960.51 h30
  text "C" at 2509.66,886.58 h30
  text "B" at 942.59,873.69 h30
  text "A" at 3624.58,551.06 h30
  text "A" at 892.56,398.95 h30
  text "B" at 3488.55,304.68 h30
  text ".Layer_Name" at 577,-858.49 h60
Top Paste:
  text ".Layer_Name" at 577,-858.49 h60
Bottom Paste:
  text ".Layer_Name" at 577,-858.49 h60
Top Solder:
  text ".Layer_Name" at 577,-858.49 h60
  text ".Layer_Name" at 577,-858.49 h60
Bottom Solder:
  text ".Layer_Name" at 577,-858.49 h60
Drill Guide:
  text ".Layer_Name" at 577,-858.49 h60
M1 Board Outline:
  the board outline again, w10
M2 Board Dimensions:
  rectangle: 0,-275 125,-150
  rectangle: 125,-400 500,-275
  lines w7: 0,-275 1000,-275 ; 125,-400 125,-150 ; 250,-400 250,-150 ; 500,-400 500,-150 ; 750,-400 750,-150 ; 0,-400 1000,-400 1000,-150 0,-150 0,-400
M3 3D STEP Top:
  text ".Layer_Name" at 577,-858.49 h60
M4 3D STEP Bottom:
  text ".Layer_Name" at 577,-858.49 h60
M5 Assembly Top:
  circle w10: c2487.75,466.74 r3.59
  circle w10: c2647.59,765.13 r3.59
  rectangle: 2043.31,227.36 2071.17,238.11
  rectangle: 2446.85,227.36 2474.71,238.11
  rectangle: 2811.02,227.36 2838.89,238.11
  rectangle: 3303.15,227.36 3331.01,238.11
  region: 4046.26,366.92 4046.26,394.78 4035.51,394.78 4035.51,366.92
  lines w10: -292,-930.17 6308,-930.17 ; -292,-726.83 6310,-726.83 ; -292,-523.5 -292,-1133.5 3713,-1133.5 6310,-1133.5 6310,-523.5 -291.5,-523.5 -291.5,-1133.5 1284,-1133.5 ; 2173,-1133.5 2173,-523.5 ; 3640,-726.83 3640,-523.5 ; 4902,-1140 4902,-937.17
  text "K" at 678.71,1746.6 h40
  text "K" at 678.71,1554.6 h40
  text "K" at 1340.29,1430.46 h30 r90
  text "+" at 354.54,1038.31 h60
  text "+" at 354.54,654.45 h60
  text "K" at 1045.09,604.21 h30 r90
  text "+" at 269.8,262.06 h60
  text "COMPONENTS MARKED 'DNP' SHOULD NOT BE POPULATED." at 1153.5,-318.5 h60
  text "ASSEMBLY VARIANT:" at 1153,-434 h60
  text ".VariantName" at 2189,-434 h60
  text "PCB VIEWED FROM TOP SIDE" at -228.5,-655.67 h60
  text "BOARD #:" at 2248,-655.67 h60
  text ".PRJ_Number" at 2793.5,-655.67 h60
  text "REV:" at 3838,-655.67 h60
  text ".PCB_Rev" at 4129.5,-655.67 h60
  text "SVN REV:" at -226,-859 h60
  text ".VersionControl_RevNumber" at 280,-859 h60
  text "TID #:" at 2248,-859 h60
  text ".TID" at 2793.5,-859 h60
  text "PLOT NAME =" at -228.5,-1064.34 h60
  text ".plot_File_Name" at 577,-1064.34 h60
  text "GENERATED    :" at 2250,-1064.34 h60
  text ".Print_Date" at 3119.5,-1064.34 h60
  text ".Print_Time" at 3848.5,-1064.34 h60
  text "TEXAS INSTRUMENTS" at 5113,-1064.34 h60
M6 Assembly Bottom:
  circle w1: c2492.57,357.21 r4.28
  circle w6: c3910.1,1954.79 r12.46
  lines w10: -292.5,-727.33 6309.5,-727.33 ; -290.5,-930.67 6309.5,-930.67 ; 1115.5,-1140.5 1115.5,-937.67 ; 2377.5,-727.33 2377.5,-524 ; 3844.5,-1134 3844.5,-524 ; 4733.5,-1134 6309,-1134 6309,-524 -292.5,-524 -292.5,-1134 2304.5,-1134 6309.5,-1134 6309.5,-524
  text "A20" at 1553.7,1722.61 h30
  text "C1" at 2701.16,1618.2 h30
  text "T1" at 2698.68,965.1 h30
  text "T20" at 1564.43,962.42 h30
  text "K" at 1016.35,578.79 h20 r270
  text "COMPONENTS MARKED 'DNP' SHOULD NOT BE POPULATED." at 6102,-318 h60
  text ".VariantName" at 5058,-434 h60
  text "ASSEMBLY VARIANT:" at 6097,-434 h60
  text ".PCB_Rev" at 1888,-656.17 h60
  text "REV:" at 2179.5,-656.17 h60
  text ".PRJ_Number" at 3224,-656.17 h60
  text "BOARD #:" at 3769.5,-656.17 h60
  text "PCB VIEWED FROM BOTTOM SIDE" at 6246,-656.17 h60
  text ".TID" at 3224,-859.5 h60
  text "TID #:" at 3769.5,-859.5 h60
  text ".VersionControl_RevNumber" at 5737.5,-859.5 h60
  text "SVN REV:" at 6243.5,-859.5 h60
  text "TEXAS INSTRUMENTS" at 904.5,-1064.84 h60
  text ".Print_Time" at 2169,-1064.84 h60
  text ".Print_Date" at 2898,-1064.84 h60
  text "GENERATED    :" at 3767.5,-1064.84 h60
  text ".plot_File_Name" at 5440.5,-1064.84 h60
  text "PLOT NAME =" at 6246,-1064.84 h60
M9 Title Sheet:
  drawing of 57 lines, arcs and shapes, not listed
  text "1" at 739.84,8036.5 h70
  text "2" at 3235.5,8036.5 h70
  text "3" at 5724.84,8036.5 h70
  text "4" at 8231.51,8036.5 h70
  text "5" at 10730.5,8036.5 h70
  text "6" at 13235.5,8036.5 h70
  text "A" at -416.5,6893.5 h70
  text "A" at 14383.5,6893.5 h70
  text "B" at -416.5,4513.5 h70
  text "B" at 14383.5,4513.5 h70
  text "C" at -416.5,2138.5 h70
  text "C" at 14383.5,2138.5 h70
  text "PROJECT TITLE:" at 11343.5,277.5 h45
  text ".PRJ_Title" at 11393.5,144.17 h70
  text "DESIGNED FOR:" at 11343.5,-23.5 h45
  text ".PRJ_Customer" at 11393.5,-163.5 h70
  text "D" at -416.5,-231.5 h70
  text "D" at 14383.5,-231.5 h70
  text "FILE NAME:" at 11343.5,-323.5 h45
  text ".PCB_File_Name_No_Path" at 11393.5,-443.5 h70
  text "Texas Instruments (TI) and/or its licensors do not warrant the accuracy or completeness of this specification" at 6374,-605.34 h45
  text "ENGINEER:" at 11343.5,-613.5 h45
  text "LAYOUT BY:" at 12848.5,-613.5 h45
  text "or any information contained therein. TI and/or its licensors do not warrant that this design will meet" at 6329.01,-718 h45
  text ".PRJ_Engineer" at 11393.5,-768.49 h70
  text ".PCB_Layout" at 12899,-768.49 h70
  text "the specifications, will be suitable for your application or fit for any particular purpose, or will operate in" at 6329.01,-830.67 h45
  text "ALTIUM DESIGNER VERSION:" at 12848.5,-923.5 h45
  text "an implementation. TI and/or its licensors do not warrant that the design is production worthy. You should" at 6329.01,-943.33 h45
  text "completely validate and test your design implementation to confirm the system functionality for your application." at 6374,-1056 h45
  text ".print_Scale" at 11393.5,-1056.83 h70
  text ".Application_BuildNumber" at 12899,-1056.83 h70
  text "1" at 739.84,-1263.5 h70
  text "2" at 3235.5,-1263.5 h70
  text "3" at 5724.84,-1263.5 h70
  text "4" at 8231.51,-1263.5 h70
  text "5" at 10730.5,-1263.5 h70
  text "6" at 12740.07,-1270 h70
  text "WO:#307812-7810-D" at 13169.89,-1271.61 h70
M10 Fab Notes:
  drawing of 300 lines, arcs and shapes, not listed
  text "FAB NOTES" at -89.84,6842.93 h60
  text "1. BOARD DIMENSION IS 107MM x 52 MM" at -89.84,6659.78 h60
  text "2. VENDOR MAY ADJUST SOLDERMASK WHEREVER SOLDERMASK PADS ARE THE SAME SIZE (1:1) AS PER THE MANUFACTURING CAPABILITIES," at -89.84,6496.63 h60
  text "DESIGN INFORMATION" at 12382.02,6356.17 h60
  text "PROVIDED NO ADJACENT COPPER IS EXPOSED AND NO CONFLICT IS PRODUCED WITH ANY STATED \"VIA TENTING/COVERING\" REQUIREMENTS." at 18.63,6302.05 h60
  text "MIN. TRACK WIDTH:" at 11737.46,6224.05 h60
  text "4" at 12833.7,6224.05 h60
  text "MIL" at 12988.46,6224.05 h60
  text "3. TRACES WITH 6.2MIL TO BE 50 OHMS +/-10% SINGLE ENDED ON L1 & L10(External Layers)." at -89.84,6130.33 h60
  text "MIL" at 12988.46,6100.92 h60
  text "MIN. CLEARANCE:" at 11737.46,6099.92 h60
  text "4" at 12832.39,6094.29 h60
  text "18" at 12811.6,5977.31 h60
  text "MIN. VIA PAD SIZE:" at 11737.46,5975.8 h60
  text "MIL" at 12988.46,5975.8 h60
  text "4. TRACES WITH 5.6MIL TO BE 50 OHMS +/-10% SINGLE ENDED ON L3 & L8(Signal Layer 1 & Signal Layer 2)." at -89.84,5947.18 h60
  text "0.05mm (2MIL)" at 12432.46,5845.9 h60
  text "MINIMUM ANNULAR RING" at 11408.23,5837.67 h60
  text "EXTERNAL" at 13140.46,5837.67 h60
  text "5. TRACES WITH 4.5MIL AND 6.5MIL SEPERATION TO BE 100 OHMS +/-10%  DIFFERENTIAL ON L1 (Top Layer)." at -89.84,5764.03 h60
  text "PER" at 11608.23,5727.55 h60
  text "IPC-D-275 CLASS 2 LEVEL C" at 11828.23,5727.54 h60
  text "MIL, HOLES" at 13316.46,5627.07 h60
  text "+/-" at 12924,5618.48 h60
  text "+/-" at 13778,5618.48 h60
  text "REGISTRATION TOLERANCES:" at 11408.23,5617.42 h60
  text "METAL" at 12608,5617.42 h60
  text "5" at 13184.2,5617.42 h60
  text "3" at 14017.2,5617.42 h60
  text "MIL" at 14133.46,5617.42 h60
  text "6. TRACES WITH 4MIL AND 7 MIL SEPERATION TO BE 100 OHMS +/-10%  DIFFERENTIAL ON L3 & L8(Signal Layer 1 & Signal Layer 2)." at -89.84,5580.88 h60
  text "HOLE SIZE TOLERANCE (UNLESS OTHERWISE SPECIFIED):" at 11408.23,5519.1 h60
  text "+/-" at 13778,5516.23 h60
  text "3" at 14017.2,5515.17 h60
  text "MIL" at 14133.46,5515.17 h60
  text "7. ALL VIAS ARE TENTED ON BOTH SIDES UNLESS OTHERWISE SOLDER MASK IS OPENED IN GERBER." at -89.84,5377.74 h60
  text "MATERIAL:" at 11333.46,5377.52 h60
  text "FR-4 High Tg" at 12319.9,5249 h60
  text "FR-4" at 13593.34,5249 h60
  text "X" at 13064.46,5241.01 h60
  text "FR-408" at 11754.46,5236.49 h60
  text "OTHER" at 13242.46,5236.49 h60
  text "8. IF NEEDED, COPPER THIEVING CAN BE ADDED BASED ON COPPER BALANCING CALCULATION" at -89.84,5206.02 h60
  text "X" at 13243.48,5093.68 h60
  text "62 MIL (1.6mm) +/-10%" at 12074.56,5093.46 h60
  text "67mil +/-10%" at 13658.01,5088.88 h60
  text "THICKNESS:" at 11408.23,5085.24 h60
  text "OTHER" at 13359.46,5085.24 h60
  text "AND MAINTAIN 100MIL SPACING FROM ANY FUNCTIONAL CONDUCTOR." at 18.63,5011.44 h60
  text "TOLERANCE:" at 11408.23,4946.92 h60
  text "X" at 12256.46,4946.92 h60
  text "ANSI IPC-6012 TYPE 3 CLASS 2" at 12434.48,4946.92 h60
  text "OTHER +/-" at 12434.46,4802.73 h60
  text "BOW & TWIST:" at 11408.23,4657.54 h60
  text "X" at 12256.46,4657.54 h60
  text "ANSI IPC-6012 TYPE 3 CLASS 2" at 12434.48,4657.54 h60
  text "OTHER +/-" at 12434.46,4510.85 h60
  text "DRILLING:" at 11333.46,4380.23 h60
  text "NC_DRILL FILES" at 13094.46,4275.04 h60
  text "REFERENCE:" at 11408.23,4271.1 h60
  text "X" at 12065.46,4271.01 h60
  text "AS SHOWN" at 12243.46,4271.1 h60
  text "X" at 12966.46,4271.1 h60
  text "OTHER" at 13392.46,4128.85 h60
  text "PTH COPPER THICKNESS:" at 11407.91,4125.32 h60
  text "X" at 12547.14,4125.32 h60
  text "20-30 um" at 12675.14,4125.32 h60
  text "BOARD FINISH:" at 11333.46,3977.73 h60
  text "SILKSCREEN:" at 11488.68,3867.6 h60
  text "X" at 12446.46,3867.6 h60
  text "TOP" at 12563.46,3867.6 h60
  text "X" at 12956.46,3867.6 h60
  text "BOTTOM" at 13074.46,3867.6 h60
  text "SILKSCREEN COLOR:" at 11488.68,3712.41 h60
  text "X" at 12445.46,3712.41 h60
  text "WHITE" at 12563.46,3712.41 h60
  text "OTHER" at 13074.46,3712.41 h60
  text "X" at 12576.46,3568.96 h60
  text "GREEN" at 12694.46,3568.96 h60
  text "OTHER" at 13312.46,3568.96 h60
  text "SOLDER RESIST COLOR:" at 11488.68,3562.1 h60
  text "BOARD CUT-OUT DETAILS:" at 4165.61,3439.34 h60
  text "X" at 12576.46,3414.71 h60
  text "MATTE" at 12694.46,3414.71 h60
  text "SEMI-GLOSS" at 13312,3414.07 h60
  text "5.89 MM" at 4443.18,3256.65 h60
  text "IMMERSION GOLD (ENIG)" at 12394.46,3241.94 h60
  text "ENEPIG" at 13732,3234.72 h60
  text "SURFACE FINISH:" at 11333.46,3233.72 h60
  text "X" at 12216.46,3233.72 h60
  text "IMM. TIN/SILVER OR EQUIV" at 11663,3096.4 h60
  text "OTHER" at 13094.46,3092.47 h60
  text "5.5 MM" at 4863.34,2963.88 h60
  text "ARRAY/PANEL:" at 11333.46,2937.09 h60
  text "CUT AND TRIM PER M1 BOARD OUTLINE" at 12394.46,2928.87 h60
  text "N.C. ROUTE" at 12394.46,2792.9 h60
  text "V. SCORE" at 13260.46,2792.9 h60
  text "CERTIFICATION:" at 11333.46,2663.77 h60
  text "MATERIALS AND WORKMANSHIP FOR ALL PCBS" at 12058.46,2663.77 h60
  text "TO MEET OR EXCEED THE REQUIREMENTS OF:" at 12058.46,2569.71 h60
  text "R 2.5MM" at 4895,2484.42 h70
  text "X" at 11695.97,2441.08 h60
  text "ANSI IPC-A-600F CLASS ->" at 11823.96,2441.08 h60
  text "X" at 13471.97,2441.08 h60
  text "2" at 13581.96,2441.08 h60
  text "1" at 13266.96,2439.58 h60
  text "3" at 13935.96,2439.58 h60
  text "X" at 12507.97,2293.39 h60
  text "RoHS" at 12635.96,2293.39 h60
  text "OTHER" at 13280.36,2293.39 h60
  text "PER ORDER" at 13677.42,2293.39 h60
  text "5.89 MM" at 4448.21,2194.1 h60
  text "ALL BOARDS MUST MEET OR EXCEED UL94-V0 REQUIREMENTS." at 11361,2139.57 h60
  text "PCB MUST BEAR THE UL94V-0 UL REGISTERED MATERIAL ID NUMBER" at 11361,2023.5 h60
  text "5.5 MM" at 4868.36,1901.34 h60
  text "ADDITIONAL REQUIREMENTS:" at 11333.46,1854.08 h60
  text "MICROSECTION:" at 11408.23,1746.95 h60
  text "YES" at 12313.96,1746.95 h60
  text "REQUIRED" at 13175.46,1602.62 h60
  text "BARE BOARD ELEC. TEST:" at 11408.23,1599.76 h60
  text "NONE" at 12713.96,1599.76 h60
  text "X" at 13057.46,1599.76 h60
  text "PER ORDER" at 13767.46,1599.76 h60
  text "XX MIL VIAS REQUIRE NON-CONDUCTIVE FILL AND PLANARIZE" at 11576.38,1394.82 h59
  text "XX MIL VIAS REQUIRE CONDUCTIVE FILL AND PLANARIZE" at 11584.38,1290.84 h60
  text "OUTER XX MIL TRACES REQUIRE 50 OHM SINGLE-ENDED IMPEDANCE" at 11583.39,1127.46 h58
  text "14 MM" at 4550.73,1028.02 h60 r90
  text "LAYER 2 & 3 (INNER LAYERS) XX MIL WIDE, XX MIL SPACE / TRACES REQUIRE 100 OHM DIFFERENTIAL IMPEDANCE" at 11575.39,891.74 h60
  text "4X R 0.75MM" at 5819.43,820.53 h70
  text "20.7 MM" at 4897.73,726.53 h60
M11 Gerber Information:
  lines w10: -292,-930.17 6308,-930.17 ; -292,-726.83 6310,-726.83 ; -292,-523.5 -292,-1133.5 3713,-1133.5 6310,-1133.5 6310,-523.5 -291.5,-523.5 -291.5,-1133.5 1284,-1133.5 ; 2173,-1133.5 2173,-523.5 ; 3540,-726.83 3540,-523.5 ; 4280,-726.83 4280,-523.5 ; 4902,-1140 4902,-937.17
  text "ALL ARTWORK VIEWED FROM TOP SIDE" at -228.5,-655.67 h60
  text "BOARD #:" at 2248,-655.67 h60
  text ".PRJ_Number" at 2793.5,-655.67 h60
  text "REV:" at 3738,-655.67 h60
  text ".PCB_Rev" at 4029.5,-655.67 h60
  text "SVN REV:" at 4476,-655.67 h60
  text ".VersionControl_RevNumber" at 4982,-655.67 h60
  text "LAYER NAME =" at -228.5,-858.49 h60
  text "TID #:" at 2248,-859 h60
  text ".TID" at 2793.5,-859 h60
  text "PLOT NAME =" at -228.5,-1064.34 h60
  text ".plot_File_Name" at 577,-1064.34 h60
  text "GENERATED    :" at 2250,-1064.34 h60
  text ".Print_Date" at 3119.5,-1064.34 h60
  text ".Print_Time" at 3848.5,-1064.34 h60
  text "TEXAS INSTRUMENTS" at 5113,-1064.34 h60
